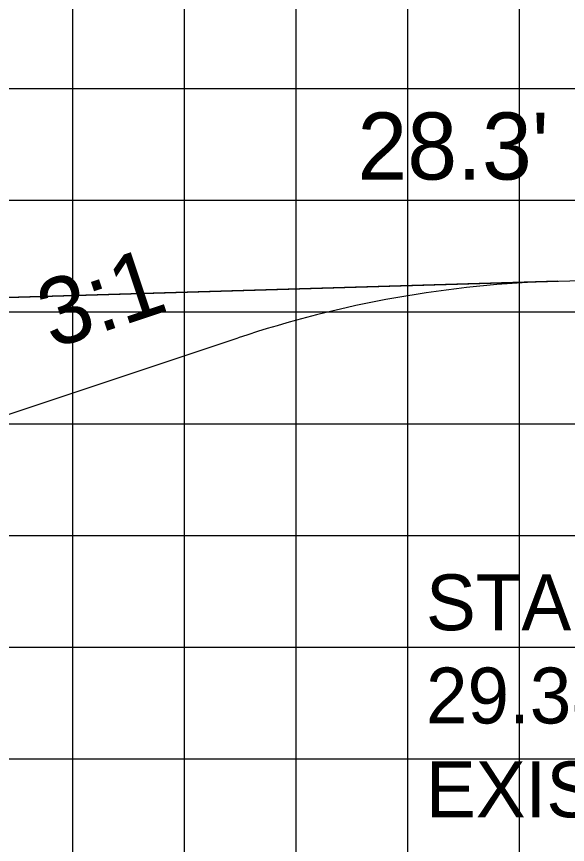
# Model space of a CAD drawing. Extents: x 856235 to 856405, y 366268 to 366378.
# Drawn here: x 856341.28 to 856346.21, y 366360.72 to 366368.12 of the extents above; entities that cross this region are included whole.
import ezdxf

# ---------------------------------------------------------------- set-up
doc = ezdxf.new("R2010")
doc.units = 0
for name, color, linetype in [('ANNOTATION', 7, 'Continuous'), ('D_Roadway_FinishedGrade', 7, 'Continuous'), ('D_Text_Monospaced', 7, 'Continuous'), ('D_Text_Standard', 7, 'Continuous'), ('JUNK COM EXC', 7, 'Continuous'), ('MAJOR', 7, 'Continuous'), ('MINOR', 7, 'Continuous'), ('S_Roadway_Centerline', 7, 'Continuous')]:
    doc.layers.add(name, color=color, linetype=linetype)

msp = doc.modelspace()

# ---------------------------------------------------------------- linework, layer by layer
at = {"layer": 'D_Roadway_FinishedGrade'}
msp.add_lwpolyline([(856340.197, 366364.228), (856343.2609, 366365.249)], dxfattribs=at)
msp.add_arc((856346.4224, 366355.7619), 10, 91.70198, 108.43008, dxfattribs=at)
at = {"layer": 'JUNK COM EXC'}
for points in [[(856346.1254, 366365.7575), (856337.467, 366365.5002), (856335.5813, 366364.7147), (856334.342, 366364.246), (856334.3076, 366364.2321), (856333.9698, 366363.9515), (856333.9139, 366363.825), (856333.6887, 366363.6273), (856329.8634, 366363.7036), (856328.9539, 366363.7085), (856326.9862, 366363.7428), (856318.1748, 366364.1168), (856309.2249, 366363.8015), (856307.4376, 366363.7326), (856301.7404, 366363.4316), (856300.9807, 366363.4041)], [(856300.9807, 366363.4041), (856300.7016, 366363.3941), (856300.5632, 366363.4298), (856296.3484, 366363.5357), (856294.3169, 366363.3781), (856292.6007, 366363.3649), (856286.2296, 366363.1169), (856265.7807, 366362.9343), (856265.7807, 366361.7676), (856290.9807, 366362.3955), (856300.9807, 366361.4387), (856306.7807, 366361.5707), (856317.7807, 366361.7907), (856328.7807, 366361.5707), (856337.781, 366361.3907), (856337.781, 366364.1797), (856340.197, 366364.228), (856343.2609, 366365.249)]]:
    msp.add_lwpolyline(points, dxfattribs=at)
msp.add_arc((856346.4224, 366355.7619), 10, 91.70198, 108.43008, dxfattribs=at)
at = {"layer": 'MAJOR'}
for p, q in [((856342.7807, 366353.481), (856342.7807, 366373.481)), ((856247.7807, 366363.481), (856387.7807, 366363.481))]:
    msp.add_line(p, q, dxfattribs=at)
at = {"layer": 'MINOR'}
for p, q in [((856341.7807, 366353.481), (856341.7807, 366373.481)), ((856343.7807, 366353.481), (856343.7807, 366373.481)), ((856344.7807, 366353.481), (856344.7807, 366373.481)), ((856345.7807, 366353.481), (856345.7807, 366373.481)), ((856247.7807, 366367.481), (856387.7807, 366367.481)), ((856247.7807, 366366.481), (856387.7807, 366366.481)), ((856247.7807, 366365.481), (856387.7807, 366365.481)), ((856247.7807, 366364.481), (856387.7807, 366364.481)), ((856247.7807, 366362.481), (856387.7807, 366362.481)), ((856247.7807, 366361.481), (856387.7807, 366361.481))]:
    msp.add_line(p, q, dxfattribs=at)
at = {"layer": 'S_Roadway_Centerline'}
msp.add_lwpolyline([(856328.9539, 366363.7085), (856329.8634, 366363.7036), (856333.6887, 366363.6273), (856333.9139, 366363.825), (856333.9698, 366363.9515), (856334.3076, 366364.2321), (856334.342, 366364.246), (856335.5813, 366364.7147), (856337.467, 366365.5002), (856349.3551, 366365.8535), (856352.5204, 366365.8869), (856356.926, 366365.9787), (856360.6227, 366365.787), (856360.7734, 366366.1618), (856360.9893, 366367.5264), (856361.1117, 366367.4114), (856361.1864, 366367.1574)], dxfattribs=at)

# ---------------------------------------------------------------- texts
at = {"layer": 'ANNOTATION'}
msp.add_text('3:1', height=0.6, rotation=18.43044, dxfattribs=at).set_placement((856341.5963, 366365.1483))
at = {"layer": 'D_Text_Monospaced'}
for s, p in [('STA. 284+23.79', (856344.9436, 366362.6329)), ('29.38 RT.', (856344.9436, 366361.7989)), ('EXIST. 24" ASH', (856344.9436, 366360.9589))]:
    msp.add_text(s, height=0.49998, dxfattribs=at).set_placement(p)
at = {"layer": 'D_Text_Standard'}
msp.add_text("28.3'", height=0.6, dxfattribs=at).set_placement((856344.3298, 366366.6658))

doc.saveas('drawing.dxf')
